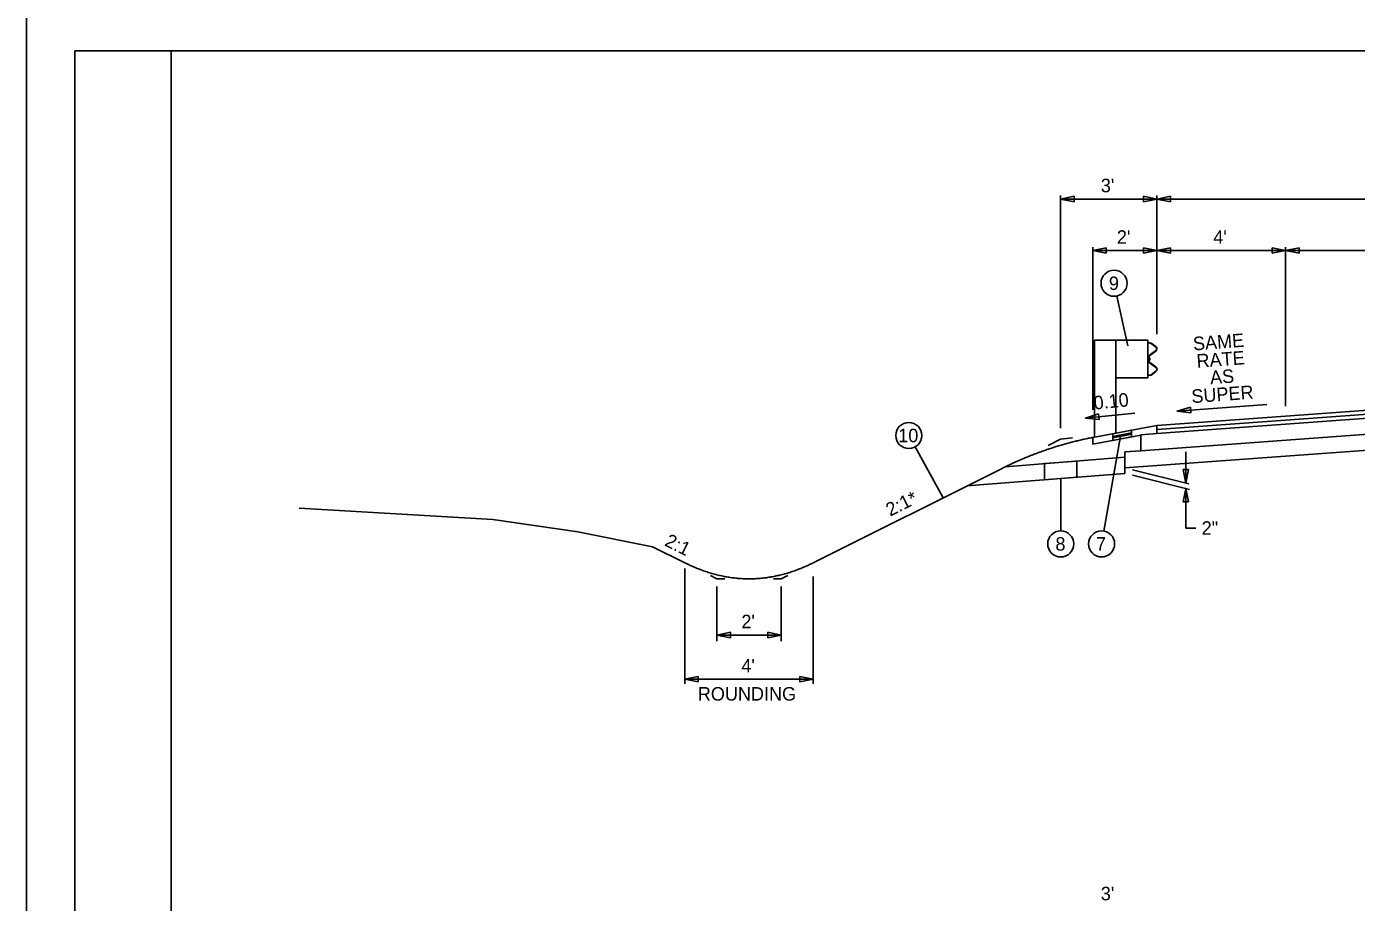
# Model space of a CAD drawing. Extents: x -345 to 102, y -108 to 100.
# Drawn here: x 0 to 41.38, y -28 to -0.75 of the extents above; entities that cross this region are included whole.
import ezdxf

# ---------------------------------------------------------------- set-up
doc = ezdxf.new("R2010")
doc.units = 0
for name, color, linetype in [('DT_X_Terrain_Ground_Line', 7, 'Continuous'), ('RD_P_Cells', 7, 'Continuous'), ('SH_Border', 7, 'Continuous'), ('SH_Cut_Line', 7, 'Continuous'), ('TX_P_1', 7, 'Continuous'), ('TX_X_1', 7, 'Continuous'), ('XS_P_Finished_Grade', 7, 'Continuous'), ('XS_P_Pavt_Surface', 7, 'Continuous')]:
    doc.layers.add(name, color=color, linetype=linetype)

msp = doc.modelspace()

# ---------------------------------------------------------------- linework, layer by layer
at = {"layer": 'DT_X_Terrain_Ground_Line'}
msp.add_lwpolyline([(19.48, -16.934), (17.153, -16.475), (14.503, -16.09), (8.477, -15.739)], dxfattribs=at)
at = {"layer": 'RD_P_Cells'}
for p, q in [((33.892, -10.512), (33.225, -10.512)), ((33.225, -13.516), (33.225, -10.512)), ((34.892, -10.512), (33.892, -10.512)), ((33.892, -13.41), (33.892, -10.512)), ((34.892, -11.68), (34.892, -10.512)), ((34.907, -10.584), (34.907, -10.584)), ((34.907, -10.584), (34.994, -10.599)), ((34.907, -10.594), (34.907, -10.584)), ((34.907, -10.594), (34.907, -10.594)), ((34.99, -10.609), (34.907, -10.594)), ((34.99, -10.609), (34.99, -10.609)), ((35.131, -10.714), (34.99, -10.609)), ((34.994, -10.599), (34.994, -10.599)), ((34.994, -10.599), (35.137, -10.706)), ((35.011, -10.625), (35.011, -10.625)), ((35.017, -10.617), (35.017, -10.617)), ((35.131, -10.714), (35.131, -10.714)), ((35.137, -10.706), (35.137, -10.706)), ((34.907, -11.05), (34.907, -11.05)), ((34.908, -11.142), (34.907, -11.05)), ((34.908, -11.127), (34.907, -11.065)), ((34.908, -11.142), (34.908, -11.142)), ((34.917, -11.05), (34.917, -11.05)), ((34.917, -11.05), (34.917, -11.142)), ((34.917, -11.127), (34.917, -11.065)), ((34.917, -11.142), (34.917, -11.142)), ((34.944, -10.978), (35.131, -10.841)), ((34.944, -10.978), (34.944, -10.978)), ((35.137, -10.849), (34.949, -10.986)), ((34.949, -10.986), (34.949, -10.986)), ((35.011, -10.929), (35.011, -10.929)), ((35.017, -10.937), (35.017, -10.937)), ((35.131, -10.841), (35.131, -10.841)), ((35.137, -10.849), (35.137, -10.849)), ((35.163, -10.777), (35.163, -10.777)), ((35.173, -10.777), (35.173, -10.777)), ((34.908, -11.598), (34.992, -11.583)), ((34.944, -11.213), (34.944, -11.213)), ((35.132, -11.35), (34.944, -11.213)), ((34.95, -11.205), (34.95, -11.205)), ((34.95, -11.205), (35.137, -11.342)), ((34.992, -11.583), (35.133, -11.477)), ((35.138, -11.485), (34.996, -11.592)), ((35.132, -11.35), (35.132, -11.35)), ((35.133, -11.477), (35.133, -11.477)), ((35.137, -11.342), (35.137, -11.342)), ((35.138, -11.485), (35.138, -11.485)), ((35.164, -11.414), (35.164, -11.414)), ((35.174, -11.414), (35.174, -11.414)), ((34.892, -11.68), (33.892, -11.68)), ((34.996, -11.592), (34.908, -11.608)), ((34.908, -11.598), (34.908, -11.598)), ((34.908, -11.608), (34.908, -11.598)), ((34.908, -11.608), (34.908, -11.608))]:
    msp.add_line(p, q, dxfattribs=at)
for points in [[(34.926, -11.036), (34.926, -11.156), (34.917, -11.156), (34.917, -11.036)], [(34.926, -11.068), (34.926, -11.126), (34.951, -11.126), (34.951, -11.068)]]:
    msp.add_lwpolyline(points, close=True, dxfattribs=at)
for centre, radius, start, end in [((35.084, -10.777), 0.0787, 306.318, 53.2212), ((35.084, -10.777), 0.0886, 306.318, 53.2212), ((34.996, -11.05), 0.0886, 126.318, 180.0944), ((34.996, -11.142), 0.0886, 180.0944, 233.8707), ((34.996, -11.05), 0.0788, 126.318, 180.0944), ((34.996, -11.142), 0.0788, 180.0944, 233.8707), ((35.085, -11.414), 0.0787, 306.9675, 53.8707), ((35.085, -11.414), 0.0886, 306.9675, 53.8707)]:
    msp.add_arc(centre, radius, start, end, dxfattribs=at)
at = {"layer": 'SH_Border'}
for points in [[(1.5, -1.5), (4.5, -1.5), (4.5, -64.5), (1.5, -64.5)], [(4.5, -1.5), (100.5, -1.5), (100.5, -64.5), (4.5, -64.5)]]:
    msp.add_lwpolyline(points, close=True, dxfattribs=at)
at = {"layer": 'SH_Cut_Line'}
msp.add_lwpolyline([(0, -66), (102, -66), (102, 0), (0, 0)], close=True, dxfattribs=at)
at = {"layer": 'TX_P_1'}
for p, q in [((32.173, -13.246), (32.173, -6.008)), ((32.173, -6.115), (35.173, -6.115)), ((32.593, -6.199), (32.593, -6.031)), ((34.753, -6.031), (34.753, -6.199)), ((35.173, -10.325), (35.173, -6.008)), ((50.173, -6.115), (35.173, -6.115)), ((35.593, -6.199), (35.593, -6.031)), ((33.173, -12.674), (33.173, -7.615)), ((35.173, -7.719), (33.173, -7.719)), ((33.593, -7.803), (33.593, -7.635)), ((34.753, -7.635), (34.753, -7.803)), ((39.173, -7.719), (35.173, -7.719)), ((35.593, -7.803), (35.593, -7.635)), ((38.753, -7.635), (38.753, -7.803)), ((39.173, -12.56), (39.173, -7.615)), ((39.173, -7.719), (50.173, -7.719)), ((39.593, -7.803), (39.593, -7.635)), ((32.947, -12.93), (34.482, -12.776)), ((33.356, -12.804), (33.373, -12.971)), ((35.8, -12.712), (38.589, -12.508)), ((36.213, -12.597), (36.225, -12.765)), ((36.068, -13.982), (36.068, -14.955)), ((34.173, -14.15), (30.453, -14.448)), ((34.173, -14.652), (29.257, -15.045)), ((34.173, -14.485), (34.173, -14.652)), ((34.407, -14.543), (36.162, -14.978)), ((34.407, -14.71), (36.182, -15.15)), ((35.984, -14.535), (36.152, -14.535)), ((36.068, -15.121), (36.068, -16.353)), ((36.152, -15.541), (35.984, -15.541)), ((36.387, -16.353), (36.068, -16.353)), ((20.48, -21.197), (20.48, -17.612)), ((21.48, -18.172), (21.48, -19.872)), ((23.48, -18.172), (23.48, -19.872)), ((24.48, -21.197), (24.48, -17.857)), ((21.48, -19.682), (23.48, -19.682)), ((21.9, -19.766), (21.9, -19.598)), ((23.06, -19.598), (23.06, -19.766)), ((20.48, -21.058), (24.48, -21.058)), ((20.9, -21.142), (20.9, -20.974)), ((24.06, -20.974), (24.06, -21.142))]:
    msp.add_line(p, q, dxfattribs=at)
for points in [[(32.593, -6.031), (32.173, -6.115), (32.593, -6.199)], [(34.753, -6.199), (35.173, -6.115), (34.753, -6.031)], [(35.593, -6.031), (35.173, -6.115), (35.593, -6.199)], [(33.593, -7.635), (33.173, -7.719), (33.593, -7.803)], [(34.753, -7.803), (35.173, -7.719), (34.753, -7.635)], [(35.593, -7.635), (35.173, -7.719), (35.593, -7.803)], [(38.753, -7.803), (39.173, -7.719), (38.753, -7.635)], [(39.593, -7.635), (39.173, -7.719), (39.593, -7.803)], [(33.373, -12.971), (32.947, -12.93), (33.356, -12.804)], [(36.225, -12.765), (35.8, -12.712), (36.213, -12.597)], [(31.783, -13.782), (32.173, -13.587), (32.548, -13.55)], [(36.152, -14.535), (36.068, -14.955), (35.984, -14.535)], [(35.984, -15.541), (36.068, -15.121), (36.152, -15.541)], [(21.277, -17.832), (21.48, -17.934), (21.722, -17.934)], [(23.682, -17.832), (23.48, -17.934), (23.237, -17.934)], [(21.9, -19.598), (21.48, -19.682), (21.9, -19.766)], [(23.06, -19.766), (23.48, -19.682), (23.06, -19.598)], [(20.9, -20.974), (20.48, -21.058), (20.9, -21.142)], [(24.06, -21.142), (24.48, -21.058), (24.06, -20.974)]]:
    msp.add_lwpolyline(points, dxfattribs=at)
msp.add_lwpolyline([(32.678, -14.27), (32.678, -14.771), (31.678, -14.851), (31.678, -14.35)], close=True, dxfattribs=at)
for centre in [(33.838, -8.737), (27.451, -13.474), (32.178, -16.847), (33.449, -16.847)]:
    msp.add_circle(centre, 0.406, dxfattribs=at)
at = {"layer": 'TX_X_1'}
for p, q in [((33.925, -9.134), (34.264, -10.689)), ((33.519, -16.447), (34.037, -13.499)), ((33.798, -13.418), (33.798, -13.543)), ((34.375, -13.311), (34.375, -13.436)), ((27.648, -13.829), (28.521, -15.413)), ((31.678, -14.851), (31.678, -14.35)), ((32.678, -14.771), (32.678, -14.27)), ((32.178, -16.441), (32.178, -14.811))]:
    msp.add_line(p, q, dxfattribs=at)
for points in [[(33.798, -13.543), (33.798, -13.418), (34.375, -13.311), (34.375, -13.436)], [(33.798, -13.627), (33.798, -13.502), (34.375, -13.394), (34.375, -13.519)]]:
    msp.add_lwpolyline(points, close=True, dxfattribs=at)
at = {"layer": 'XS_P_Finished_Grade'}
for p, q in [((30.354, -14.497), (24.48, -17.434)), ((20.48, -17.434), (19.48, -16.934))]:
    msp.add_line(p, q, dxfattribs=at)
for points in [[(30.354, -14.497), (30.424, -14.462), (30.494, -14.428), (30.564, -14.394), (30.635, -14.361), (30.706, -14.328), (30.776, -14.296), (30.847, -14.265), (30.918, -14.234), (30.99, -14.203), (31.061, -14.173), (31.133, -14.144), (31.204, -14.115), (31.276, -14.086), (31.348, -14.058), (31.42, -14.031), (31.493, -14.004), (31.565, -13.978), (31.638, -13.952), (31.71, -13.926), (31.783, -13.902), (31.856, -13.877), (31.93, -13.854), (32.003, -13.83), (32.076, -13.808), (32.15, -13.786), (32.224, -13.764), (32.298, -13.743), (32.372, -13.722), (32.446, -13.702), (32.521, -13.683), (32.595, -13.664), (32.67, -13.645), (32.745, -13.627), (32.82, -13.61), (32.895, -13.593), (32.97, -13.576), (33.046, -13.56), (33.122, -13.545), (33.173, -13.535)], [(20.48, -17.434), (20.557, -17.471), (20.633, -17.508), (20.71, -17.543), (20.787, -17.576), (20.864, -17.608), (20.941, -17.638), (21.018, -17.667), (21.095, -17.694), (21.172, -17.72), (21.249, -17.744), (21.326, -17.767), (21.403, -17.789), (21.48, -17.809), (21.557, -17.827), (21.633, -17.844), (21.71, -17.86), (21.787, -17.874), (21.864, -17.886), (21.941, -17.898), (22.018, -17.907), (22.095, -17.915), (22.172, -17.922), (22.249, -17.927), (22.326, -17.931), (22.403, -17.933), (22.48, -17.934), (22.557, -17.933), (22.633, -17.931), (22.71, -17.927), (22.787, -17.922), (22.864, -17.915), (22.941, -17.907), (23.018, -17.898), (23.095, -17.886), (23.172, -17.874), (23.249, -17.86), (23.326, -17.844), (23.403, -17.827), (23.48, -17.809), (23.557, -17.789), (23.633, -17.767), (23.71, -17.744), (23.787, -17.72), (23.864, -17.694), (23.941, -17.667), (24.018, -17.638), (24.095, -17.608), (24.172, -17.576), (24.249, -17.543), (24.326, -17.508), (24.403, -17.471), (24.48, -17.434)]]:
    msp.add_spline(points, degree=3, dxfattribs=at)
at = {"layer": 'XS_P_Pavt_Surface'}
for p, q in [((50.173, -12.067), (35.173, -13.162)), ((50.173, -12.192), (35.173, -13.287)), ((50.173, -12.317), (35.173, -13.412)), ((50.173, -12.817), (34.673, -13.949)), ((35.173, -13.162), (33.173, -13.535)), ((35.173, -13.162), (35.173, -13.412)), ((34.673, -13.464), (33.173, -13.743)), ((33.173, -13.535), (33.173, -13.743)), ((50.173, -13.317), (34.173, -14.485)), ((35.173, -13.412), (34.673, -13.449)), ((34.673, -13.449), (34.673, -13.949)), ((34.673, -13.949), (34.173, -13.985)), ((34.173, -13.985), (34.173, -14.485))]:
    msp.add_line(p, q, dxfattribs=at)

# ---------------------------------------------------------------- texts
at = {"layer": 'TX_P_1'}
for s, p in [("3'", (33.425, -5.905)), ("2'", (33.925, -7.509)), ("4'", (36.925, -7.509)), ('9', (33.677, -8.947)), ('10', (27.122, -13.684)), ('2"', (36.563, -16.563)), ('8', (32.013, -17.057)), ('7', (33.274, -17.057)), ("2'", (22.241, -19.472)), ("4'", (22.241, -20.848)), ('ROUNDING', (20.886, -21.723)), ("3'", (33.425, -27.938))]:
    msp.add_text(s, height=0.42, dxfattribs=at).set_placement(p)
for s, rotation, p in [('SAME', 4.1752, (36.309, -10.829)), ('RATE', 4.1752, (36.419, -11.366)), ('AS', 4.1752, (36.839, -11.88)), ('SUPER', 4.1752, (36.26, -12.468)), ('2:1*', 26.5651, (26.87, -16.004)), ('2:1', 333.4349, (19.823, -16.887))]:
    msp.add_text(s, height=0.42, rotation=rotation, dxfattribs=at).set_placement(p)
at = {"layer": 'XS_P_Finished_Grade'}
msp.add_text('0.10', height=0.42, rotation=5.7106, dxfattribs=at).set_placement((33.223, -12.671))

doc.saveas('drawing.dxf')
